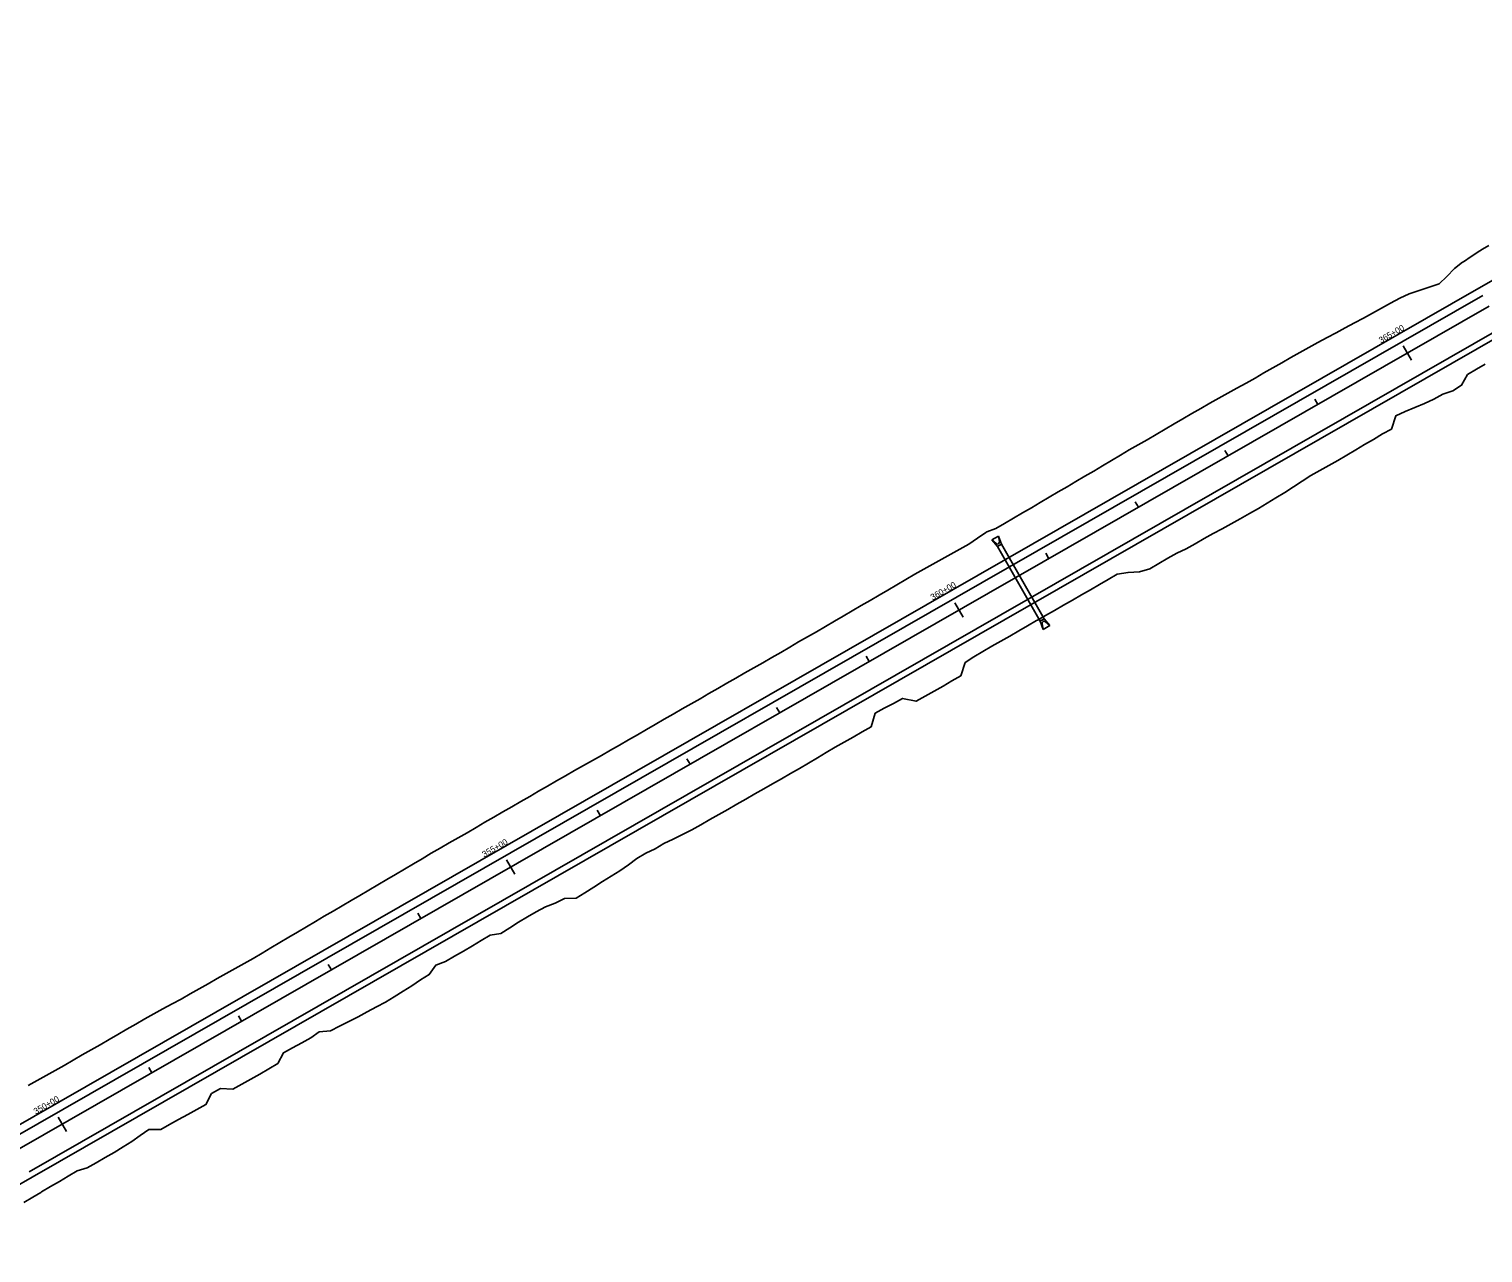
# Model space of a CAD drawing. Extents: x 1375694 to 1433473, y 1931050 to 1967991.
# Drawn here: x 1420978 to 1422385, y 1957684 to 1958868 of the extents above; entities that cross this region are included whole.
import ezdxf

# ---------------------------------------------------------------- set-up
doc = ezdxf.new("R2010")
doc.units = 0
for name, color, linetype in [('R_Drainage', 7, 'Continuous'), ('R_Horz Alg', 7, 'Continuous'), ('R_Horz Alg Annot', 7, 'Continuous'), ('R_Proposed Const Limits', 7, 'Continuous'), ('R_Proposed Road', 7, 'Continuous')]:
    doc.layers.add(name, color=color, linetype=linetype)

msp = doc.modelspace()

# ---------------------------------------------------------------- linework, layer by layer
at = {"layer": 'R_Drainage'}
for p, q in [((1421916, 1958377.7), (1421909.5, 1958374)), ((1421918.9, 1958369.7), (1421916, 1958377.7)), ((1421917, 1958372.3), (1421916, 1958377.7)), ((1421915, 1958367.5), (1421909.5, 1958374)), ((1421913.7, 1958370.4), (1421909.5, 1958374)), ((1421918.9, 1958369.7), (1421915, 1958367.5)), ((1421956.4, 1958295.4), (1421915, 1958367.5)), ((1421960.3, 1958297.6), (1421918.9, 1958369.7)), ((1421956.4, 1958295.4), (1421960.3, 1958297.6)), ((1421956.4, 1958295.4), (1421959.2, 1958287.4)), ((1421958.3, 1958292.8), (1421959.2, 1958287.4)), ((1421960.3, 1958297.6), (1421965.7, 1958291.2)), ((1421961.5, 1958294.7), (1421965.7, 1958291.2)), ((1421959.2, 1958287.4), (1421965.7, 1958291.2))]:
    msp.add_line(p, q, dxfattribs=at)
for centre, start, end in [((1421915, 1958371.9), 229.7766, 10.0937), ((1421960.2, 1958293.2), 49.7766, 190.0937)]:
    msp.add_arc(centre, 2, start, end, dxfattribs=at)
at = {"layer": 'R_Horz Alg'}
msp.add_line((1420966.4, 1957783.3), (1422390.6, 1958600.1), dxfattribs=at)
at = {"layer": 'R_Horz Alg Annot'}
for points in [[(1422307.6, 1958561.8), (1422315.6, 1958547.9)], [(1422221.9, 1958510.3), (1422224.9, 1958505.1)], [(1422135.1, 1958460.5), (1422138.1, 1958455.3)], [(1422048.4, 1958410.8), (1422051.4, 1958405.6)], [(1421961.7, 1958361), (1421964.6, 1958355.8)], [(1421873.9, 1958313), (1421881.9, 1958299.1)], [(1421788.2, 1958261.5), (1421791.1, 1958256.3)], [(1421701.4, 1958211.8), (1421704.4, 1958206.6)], [(1421614.7, 1958162), (1421617.7, 1958156.8)], [(1421527.9, 1958112.3), (1421530.9, 1958107.1)], [(1421440.2, 1958064.3), (1421448.1, 1958050.4)], [(1421354.4, 1958012.8), (1421357.4, 1958007.6)], [(1421267.7, 1957963), (1421270.7, 1957957.8)], [(1421180.9, 1957913.3), (1421183.9, 1957908.1)], [(1421094.2, 1957863.5), (1421097.2, 1957858.3)], [(1421006.4, 1957815.5), (1421014.4, 1957801.6)]]:
    msp.add_lwpolyline(points, dxfattribs=at)
at = {"layer": 'R_Proposed Const Limits'}
for points in [[(1420977.4, 1957846.1), (1420986.2, 1957850.9), (1420995, 1957855.7), (1421003.7, 1957860.6), (1421012.3, 1957865.5), (1421021, 1957870.5), (1421029.6, 1957875.6), (1421038.3, 1957880.6), (1421047, 1957885.5), (1421055.7, 1957890.5), (1421064.3, 1957895.5), (1421073, 1957900.5), (1421081.6, 1957905.5), (1421090.3, 1957910.5), (1421099, 1957915.5), (1421107.8, 1957920.2), (1421116.6, 1957924.9), (1421125.5, 1957929.6), (1421134.1, 1957934.6), (1421142.8, 1957939.5), (1421151.5, 1957944.5), (1421160.2, 1957949.4), (1421168.9, 1957954.3), (1421177.6, 1957959.3), (1421186.3, 1957964.1), (1421195.1, 1957969), (1421203.7, 1957974.1), (1421212.3, 1957979.2), (1421220.9, 1957984.3), (1421229.5, 1957989.4), (1421238.1, 1957994.5), (1421246.7, 1957999.6), (1421255.3, 1958004.7), (1421263.9, 1958009.8), (1421272.6, 1958014.8), (1421281.2, 1958019.9), (1421289.8, 1958024.9), (1421298.4, 1958030), (1421307.1, 1958035.1), (1421315.7, 1958040.1), (1421324.3, 1958045.2), (1421332.9, 1958050.3), (1421341.5, 1958055.4), (1421350.1, 1958060.5), (1421358.7, 1958065.5), (1421367.3, 1958070.7), (1421376, 1958075.7), (1421384.6, 1958080.7), (1421393.3, 1958085.7), (1421402.1, 1958090.4), (1421410.7, 1958095.6), (1421419.3, 1958100.7), (1421427.9, 1958105.8), (1421436.6, 1958110.8), (1421445.2, 1958115.7), (1421453.9, 1958120.7), (1421462.6, 1958125.7), (1421471.2, 1958130.7), (1421479.9, 1958135.7), (1421488.6, 1958140.7), (1421497.2, 1958145.7), (1421505.9, 1958150.7), (1421514.5, 1958155.7), (1421523.3, 1958160.6), (1421532, 1958165.5), (1421540.7, 1958170.5), (1421549.3, 1958175.4), (1421558, 1958180.4), (1421566.7, 1958185.4), (1421575.4, 1958190.4), (1421584, 1958195.4), (1421592.6, 1958200.4), (1421601.3, 1958205.4), (1421610, 1958210.4), (1421618.7, 1958215.3), (1421627.4, 1958220.3), (1421636, 1958225.3), (1421644.7, 1958230.3), (1421653.4, 1958235.2), (1421662.1, 1958240.2), (1421670.7, 1958245.2), (1421679.4, 1958250.2), (1421688.1, 1958255.1), (1421696.7, 1958260.1), (1421705.4, 1958265.1), (1421714.1, 1958270.1), (1421722.7, 1958275.2), (1421731.4, 1958280.2), (1421740, 1958285.1), (1421748.7, 1958290.2), (1421757.3, 1958295.3), (1421765.9, 1958300.3), (1421774.5, 1958305.4), (1421783.2, 1958310.4), (1421791.8, 1958315.5), (1421800.5, 1958320.5), (1421809.1, 1958325.5), (1421817.7, 1958330.5), (1421826.3, 1958335.7), (1421835, 1958340.7), (1421843.7, 1958345.7), (1421852.4, 1958350.5), (1421861.2, 1958355.3), (1421869.9, 1958360.2), (1421878.7, 1958365), (1421887.4, 1958369.9), (1421895.7, 1958375.5), (1421903.9, 1958381.3), (1421904.7, 1958381.9), (1421913.4, 1958384.9), (1421922, 1958390), (1421930.6, 1958395), (1421939.3, 1958400.1), (1421947.9, 1958405.1), (1421956.5, 1958410.3), (1421965.1, 1958415.3), (1421973.7, 1958420.4), (1421982.4, 1958425.4), (1421991, 1958430.4), (1421999.6, 1958435.6), (1422008.3, 1958440.6), (1422016.8, 1958445.7), (1422025.5, 1958450.7), (1422034, 1958455.9), (1422042.6, 1958461.1), (1422051.3, 1958466), (1422060, 1958470.9), (1422068.7, 1958475.9), (1422077.2, 1958481.1), (1422085.9, 1958486.2), (1422094.5, 1958491.2), (1422103.1, 1958496.2), (1422111.8, 1958501.2), (1422120.5, 1958506.2), (1422129.2, 1958511.2), (1422137.8, 1958516.1), (1422146.7, 1958520.9), (1422155.5, 1958525.6), (1422164.2, 1958530.5), (1422172.8, 1958535.5), (1422181.5, 1958540.5), (1422190.2, 1958545.4), (1422198.9, 1958550.4), (1422207.6, 1958555.3), (1422216.3, 1958560.2), (1422225.1, 1958565), (1422233.9, 1958569.7), (1422242.7, 1958574.4), (1422251.5, 1958579.2), (1422260.3, 1958584), (1422269.1, 1958588.7), (1422277.9, 1958593.5), (1422286.7, 1958598.3), (1422295.4, 1958603.2), (1422304.2, 1958607.9), (1422313.3, 1958612.2), (1422323.1, 1958615.2), (1422332.8, 1958618.4), (1422342.4, 1958621.7), (1422349.8, 1958629), (1422357, 1958636.5), (1422365, 1958642.6), (1422365.9, 1958643.2), (1422373.4, 1958648.2), (1422381.8, 1958653.7), (1422384.4, 1958655.2), (1422390.5, 1958658.8)], [(1422022.2, 1958335.8), (1422030.9, 1958340.7), (1422041.4, 1958342.5), (1422052.6, 1958343.2), (1422062.5, 1958346), (1422071.1, 1958351.1), (1422079.7, 1958356.2), (1422088.5, 1958361), (1422097.5, 1958365.3), (1422106.3, 1958370.1), (1422114.9, 1958375.3), (1422123.6, 1958380.2), (1422132.5, 1958384.8), (1422141.2, 1958389.6), (1422149.9, 1958394.5), (1422158.7, 1958399.4), (1422167.4, 1958404.3), (1422175.9, 1958409.6), (1422184.4, 1958414.8), (1422193, 1958420), (1422201.5, 1958425.3), (1422209.8, 1958430.9), (1422218.2, 1958436.3), (1422227, 1958441), (1422235.7, 1958446), (1422244.4, 1958450.9), (1422253, 1958456), (1422261.6, 1958461.1), (1422270.2, 1958466.3), (1422278.9, 1958471.3), (1422287.4, 1958476.5), (1422296.2, 1958481.2), (1422300.3, 1958494.2), (1422309.5, 1958498.2), (1422318.8, 1958502.2), (1422328, 1958506.1), (1422337.2, 1958510.3), (1422346, 1958515), (1422355.6, 1958518.3), (1422364, 1958523.7), (1422369.6, 1958534.2)], [(1422369.6, 1958534.2), (1422378.3, 1958539.1), (1422386.9, 1958544.1)], [(1421892.3, 1958260.9), (1421900.8, 1958266.1), (1421909.5, 1958271), (1421918.2, 1958275.9), (1421926.9, 1958280.9), (1421935.6, 1958285.9), (1421944.2, 1958290.9), (1421952.9, 1958295.9), (1421953.8, 1958296.4), (1421961.6, 1958300.8), (1421970.3, 1958305.8), (1421979, 1958310.8), (1421987.6, 1958315.7), (1421996.3, 1958320.7), (1422005, 1958325.6), (1422013.6, 1958330.7), (1422022.2, 1958335.8)], [(1421024.9, 1957763.3), (1421034.6, 1957766.4), (1421043.3, 1957771.3), (1421052, 1957776.2), (1421060.7, 1957781.2), (1421069.2, 1957786.6), (1421077.7, 1957791.8), (1421085.9, 1957797.6), (1421094.1, 1957803.4), (1421105.6, 1957803.5), (1421114.3, 1957808.4), (1421123, 1957813.2), (1421131.8, 1957818), (1421140.6, 1957822.8), (1421149.4, 1957827.6), (1421154.9, 1957838.1), (1421163.5, 1957843.1), (1421175.5, 1957842.3), (1421184.2, 1957847.2), (1421192.9, 1957852.2), (1421201.6, 1957857.1), (1421210.2, 1957862.2), (1421218.8, 1957867.4), (1421224.4, 1957877.7), (1421233.2, 1957882.4), (1421242, 1957887.2), (1421250.7, 1957892.2), (1421259, 1957897.8), (1421269.8, 1957899), (1421278.7, 1957903.5), (1421287.7, 1957908), (1421296.6, 1957912.6), (1421305.5, 1957917.3), (1421314.3, 1957922), (1421323.1, 1957926.8), (1421331.6, 1957931.9), (1421340.2, 1957937.2), (1421348.6, 1957942.5), (1421356.9, 1957948.1), (1421365.4, 1957953.4), (1421371.7, 1957962.5), (1421381.2, 1957966.1), (1421389.9, 1957971), (1421398.6, 1957975.9), (1421407.2, 1957981), (1421415.7, 1957986.4), (1421424.3, 1957991.5), (1421434.8, 1957993.2), (1421443.3, 1957998.5), (1421451.6, 1958004.1), (1421460.3, 1958009.1), (1421468.9, 1958014.2), (1421477.8, 1958018.8), (1421487.2, 1958022.5), (1421496.2, 1958026.9), (1421507.6, 1958027.2), (1421516, 1958032.5), (1421524.5, 1958037.9), (1421532.9, 1958043.3), (1421541.4, 1958048.6), (1421549.9, 1958053.8), (1421558.1, 1958059.6), (1421566.1, 1958065.7), (1421574.8, 1958070.7), (1421583.8, 1958075.1), (1421592.4, 1958080.2), (1421601.5, 1958084.5), (1421610.5, 1958088.8), (1421619.4, 1958093.4), (1421628.2, 1958098.3), (1421636.8, 1958103.3), (1421645.5, 1958108.3), (1421654.2, 1958113.2), (1421662.9, 1958118.2), (1421671.6, 1958123.1), (1421680.3, 1958128.1), (1421689, 1958133), (1421697.6, 1958137.9), (1421706.3, 1958142.9), (1421715, 1958147.8), (1421723.7, 1958152.9), (1421732.3, 1958158), (1421740.9, 1958163.1), (1421749.5, 1958168.2), (1421758.1, 1958173.3), (1421766.7, 1958178.3), (1421775.4, 1958183.2), (1421784.1, 1958188.1), (1421792.8, 1958193.2), (1421796.8, 1958206.3), (1421805.6, 1958211.1), (1421814.4, 1958215.8), (1421823.2, 1958220.6), (1421836.3, 1958217.8), (1421845, 1958222.7), (1421853.7, 1958227.6), (1421862.4, 1958232.6), (1421871, 1958237.7), (1421879.7, 1958242.6), (1421883.9, 1958255.3), (1421892.3, 1958260.9)], [(1420973.1, 1957732.9), (1420981.8, 1957737.9), (1420989.7, 1957742.6), (1420990.4, 1957743), (1420999, 1957748.1), (1421007.6, 1957753.2), (1421016.2, 1957758.2), (1421024.9, 1957763.3)]]:
    msp.add_lwpolyline(points, dxfattribs=at)
at = {"layer": 'R_Proposed Road'}
for p, q in [((1420956.4, 1957800.7), (1422380.7, 1958617.5)), ((1420960.4, 1957793.7), (1422384.7, 1958610.5)), ((1420978.3, 1957762.5), (1422402.6, 1958579.3)), ((1420981.3, 1957757.3), (1422405.5, 1958574.1)), ((1418119.9, 1956117.4), (1420981.3, 1957757.3))]:
    msp.add_line(p, q, dxfattribs=at)
msp.add_arc((1428091.5, 1948659.7), 11479.2, 117.21194, 119.83429, dxfattribs=at)

# ---------------------------------------------------------------- texts
at = {"layer": 'R_Horz Alg Annot'}
for s, p in [('365+00', (1422286, 1958564)), ('360+00', (1421852.3, 1958315.3)), ('355+00', (1421418.6, 1958066.5)), ('350+00', (1420984.8, 1957817.8))]:
    msp.add_text(s, height=6, rotation=29.8343, dxfattribs=at).set_placement(p)

doc.saveas('drawing.dxf')
